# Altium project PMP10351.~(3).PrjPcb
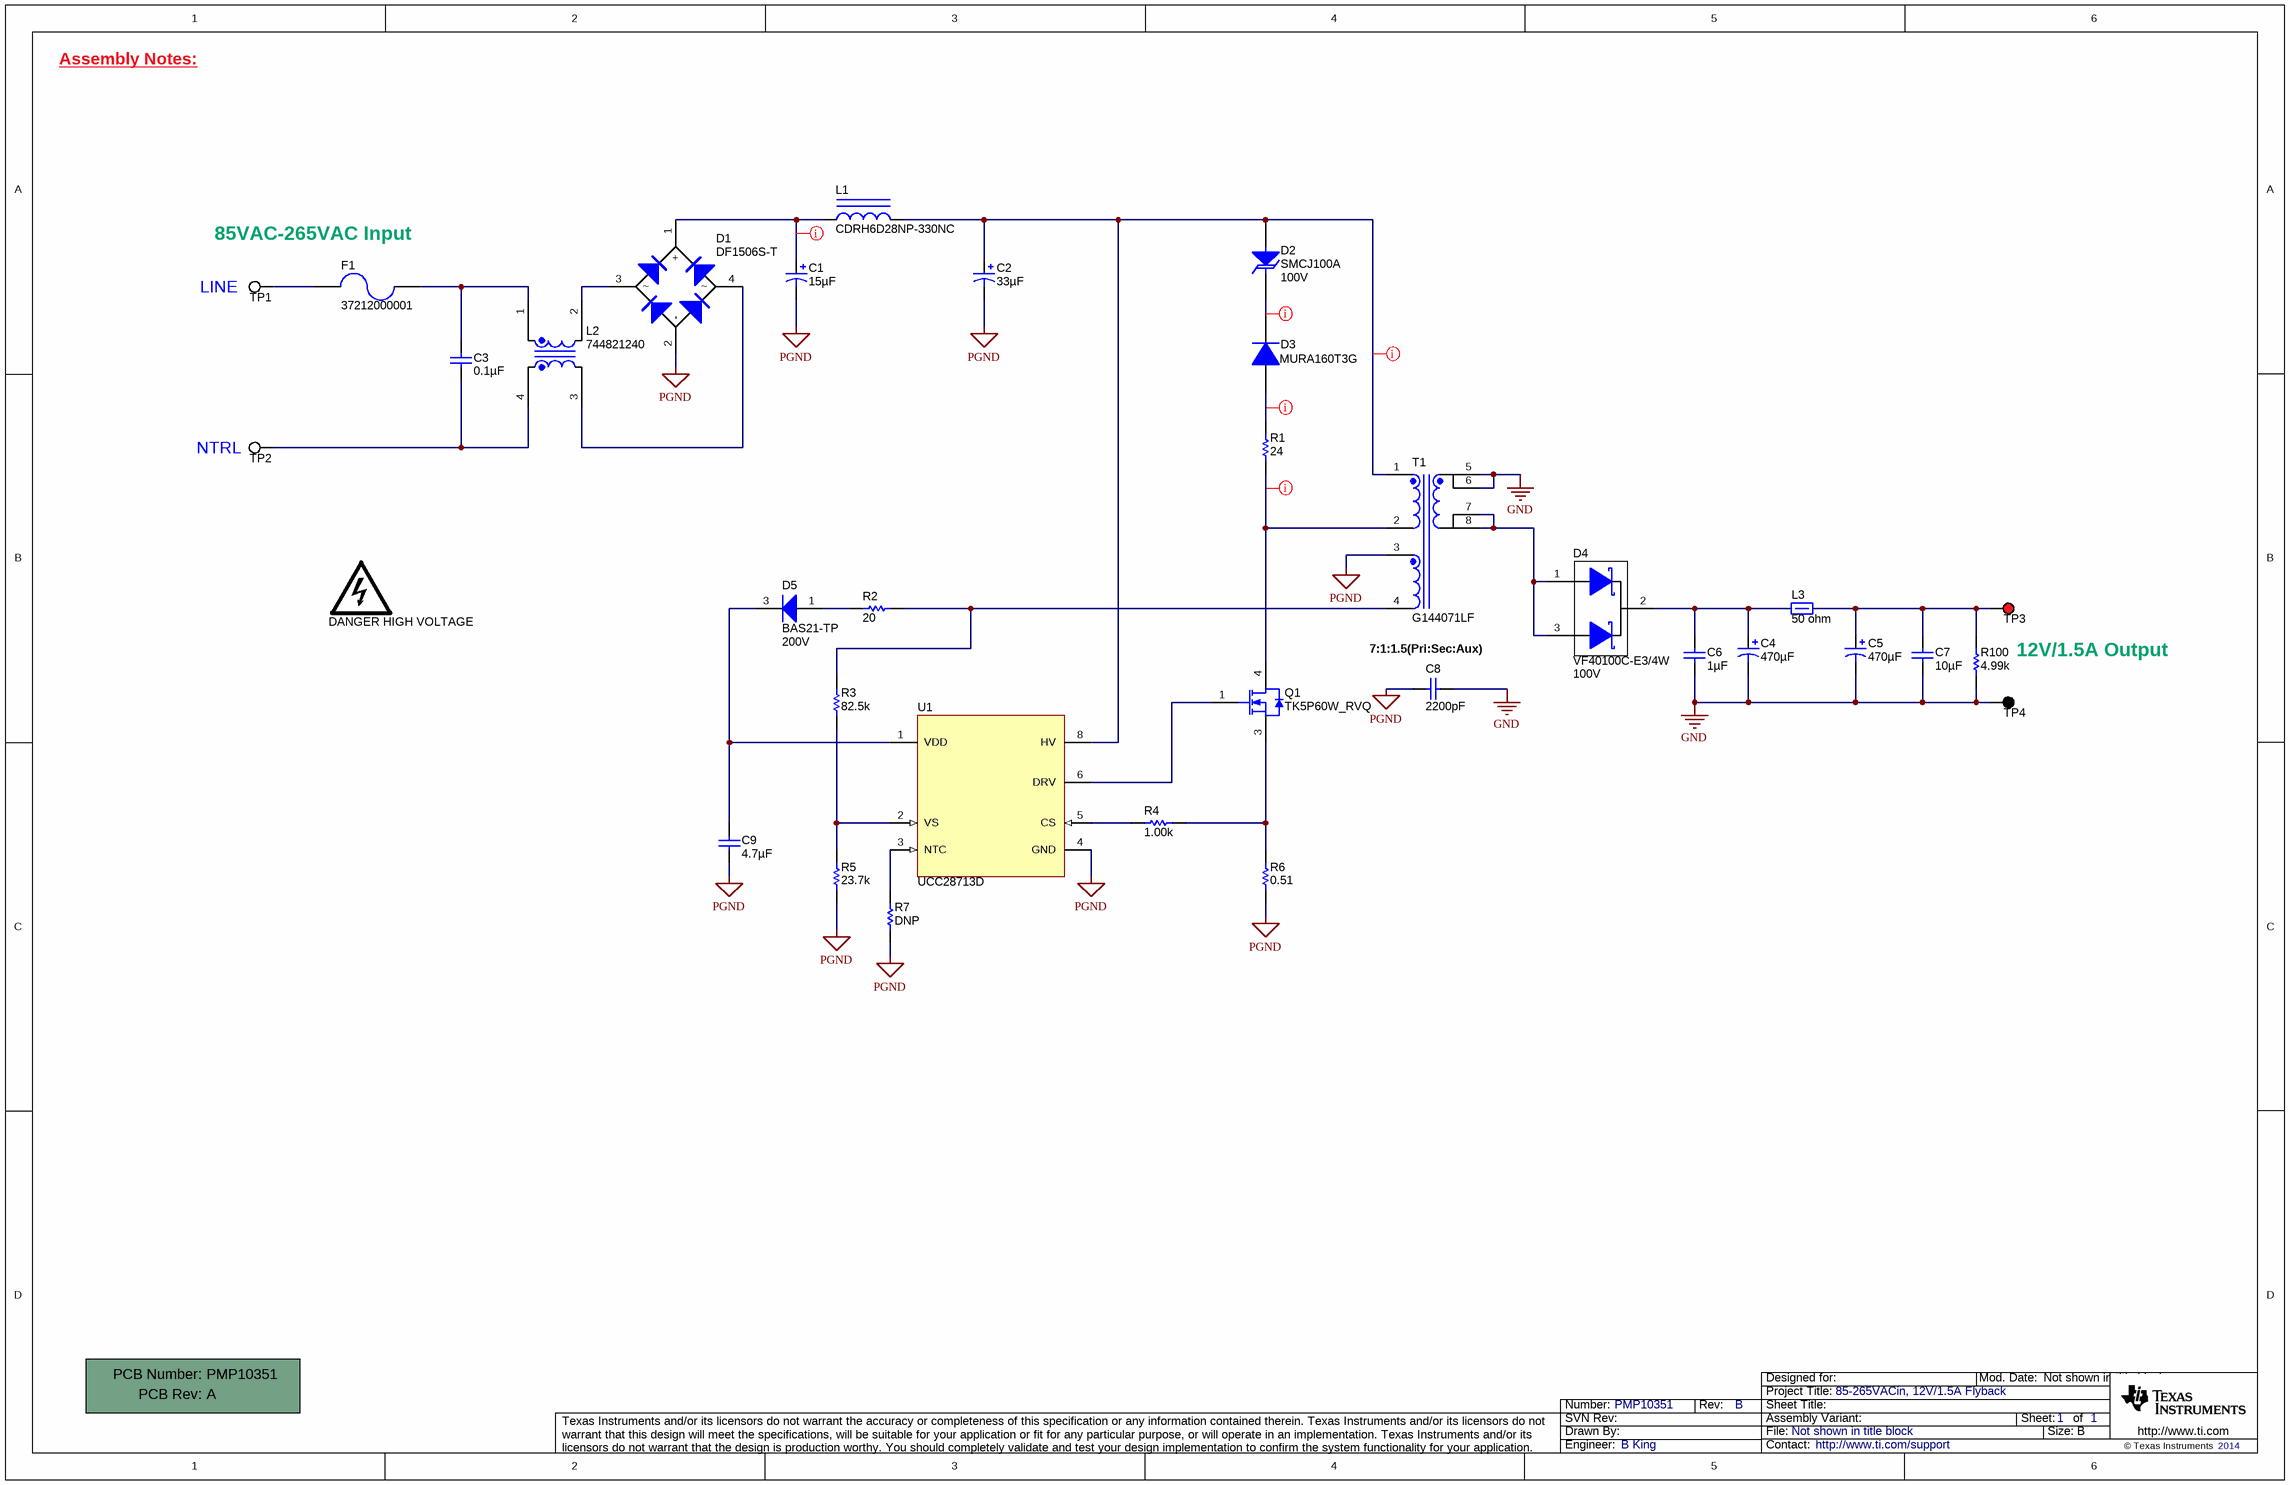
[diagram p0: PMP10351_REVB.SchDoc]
TechSupport: http://www.ti.com/support; SCH_Rev: B; PRJ_Title: 85-265VACin, 12V/1.5A Flyback; PRJ_Number: PMP10351; PRJ_Engineer: B King; PCB_Rev: A; PCB_Layout: B King; CopyrightYear: 2014
1 sheet, 35 parts. Net scope: global (net labels, ports and power ports of the same name join across sheets).
Board file: PMP10351_REVA.PcbDoc

## Sheet PMP10351_REVB.SchDoc
size 431 x 279 mm; Date: Not shown in title block; ApprovedBy: Not shown in title block; CheckedBy: Not shown in title block; Author: Not shown in title block; CompanyName: Not shown in title block; Engineer: Not shown in title block; Organization: Not shown in title block; Address1: Not shown in title block; Address2: Not shown in title block; Address3: Not shown in title block; Address4: Not shown in title block; DocumentNumber: 1; Revision: Use project parameter SCH_Rev; SheetNumber: 1; SheetTotal: 1; PageSetup: Record=PageOptions¦CenterHorizontal=True¦CenterVertical=True¦PrintScale=1.00¦XCorrection=1.00¦YCorrection=1.00¦PrintKind=0¦BorderSize=5000000¦LeftOffset=0¦BottomOffset=0¦Orientation=2¦PaperLength=1000¦PaperWidth=1000¦Scale=100¦PaperSource=15¦PrintQuality=600¦MediaType=1¦DitherType=10¦PaperKind=Letter¦PrintScaleMode=1

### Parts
!PCB1  Printed Circuit Board  (value not drawn)  (mechanical)
C1  ValueDisplayed: 15µF  [CAPPR5-12.5X20]  (hidden comment: EEUED2G150)
C2  ValueDisplayed: 33µF  [CAPPR7.5-16X20]  (hidden comment: EEUED2G330S)
C3  ValueDisplayed: 0.1µF  [B32922_10.5mm]  (hidden comment: B32922C3104M)
C4  ValueDisplayed: 470µF  [ZLG_800x1600]  (hidden comment: 16ZLG470MEFC8X16)
C5  ValueDisplayed: 470µF  [ZLG_800x1600]  (hidden comment: 16ZLG470MEFC8X16)
C6  ValueDisplayed: 1µF  [0603L]  (hidden comment: GRM188R61E105KA12D)
C7  ValueDisplayed: 10µF  [0805L]  (hidden comment: GRM21BR61E106MA73)
C8  ValueDisplayed: 2200pF  [CAPRD500W60D800H850]  (hidden comment: DE2E3KY222MA2BM01)
C9  ValueDisplayed: 4.7µF  [1206L]  (hidden comment: GRM319R61H475KA12)
D1  DF1506S-T  [DF-S]
D2  SMCJ100A  value 100V  [SMC]
D3  MURA160T3G  [SMA]
D4  VF40100C-E3/4W  value 100V  [TO-220AB]
D5  BAS21-TP  value 200V  [SOT-23L]
F1  37212000001  [FUSE_372]
L1  CDRH6D28NP-330NC  [CDRH6D28]
L2  744821240  [WE-CMB_XS]
L3  value 50 ohm  [1206L]  (hidden comment: HI1206T500R-10)
LOGO1  DANGER HIGH VOLTAGE  [IEC_HighVoltage_Small]  (no BOM)
Q1  TK5P60W_RVQ  [DPAK]
R1  value 24  [2010L]  (hidden comment: CRCW201024R0JNEF)
R2  ValueDisplayed: 20  [0603L]  (hidden comment: CRCW060320R0JNEA)
R3  ValueDisplayed: 82.5k  [0402L]  (hidden comment: CRCW040282K5FKED)
R4  ValueDisplayed: 1.00k  [0402L]  (hidden comment: CRCW04021K00FKED)
R5  ValueDisplayed: 23.7k  [0402L]  (hidden comment: CRCW040223K7FKED)
R6  value 0.51  [0805L]  (hidden comment: CRM0805-FX-R510ELF)
R7  value DNP  [0603L]  (hidden comment: N/A)
R100  ValueDisplayed: 4.99k  [0402L]  (hidden comment: CRCW04024K99FKED)
T1  G144071LF  [GCI_G144071LF]
TP1  5012  [Keystone5012]  (value not drawn)
TP2  5012  [Keystone5012]  (value not drawn)
TP3  5010  [Keystone5010]  (value not drawn)
TP4  5011  [Keystone5011]  (value not drawn)
U1  UCC28713D  [D0007A_L]

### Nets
GND: C4.2(-) C5.2(-) C6.2 C7.2 C8.1 R100.2 T1.5 T1.6 TP4.1
PGND: C1.2(-) C2.2(-) C8.2 C9.2 D1.2(-) R5.1 R6.1 R7.1 T1.3 U1.4(GND)
NetC1_1: C1.1(+) D1.1(+) L1.1
NetC2_1: C2.1(+) D2.2(A) L1.2 T1.1 U1.8(HV)
NetC3_1: C3.1 F1.1 L2.1
NetC3_2: C3.2 L2.4 TP2.1
NetC4_1: C4.1(+) C6.1 D4.2(K) L3.1
NetC5_1: C5.1(+) C7.1 L3.2 R100.1 TP3.1
NetC9_1: C9.1 D5.3(K) U1.1(VDD)
NetD1_3: D1.3 L2.2
NetD1_4: D1.4 L2.3
NetD2_1: D2.1(K) D3.1(K)
NetD3_2: D3.2(A) R1.2
NetD4_1: D4.1(A) D4.3(A) T1.7 T1.8
NetD5_1: D5.1(A) R2.2
NetF1_2: F1.2 TP1.1
NetQ1_1: Q1.1(G) U1.6(DRV)
NetQ1_3: Q1.3(S) R4.1 R6.2
NetQ1_4: Q1.4(D) R1.1 T1.2
NetR2_1: R2.1 R3.2 T1.4
NetR3_1: R3.1 R5.2 U1.2(VS)
NetR4_2: R4.2 U1.5(CS)
NetR7_2: R7.2 U1.3(NTC)

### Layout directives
rule Clearance Constraint [Clearance = 24mil]: NetQ1_4
rule Clearance Constraint [Clearance = 25mil]: NetC1_1, NetC2_1, NetD2_1, NetD3_2

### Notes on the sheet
- Assembly Notes:
- 85VAC-265VAC Input
- (near TP1) LINE
- (near TP2) NTRL
- 7:1:1.5(Pri:Sec:Aux)
- 12V/1.5A Output

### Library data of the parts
!PCB1 = PCB: Manufacturer: Any; PartNumber: PMP10351; SymbolCreator: a0412235
C1 = EEUED2G150: CAP, AL, 15uF, 400V, +/-20%, 1.909859 ohm, TH; Manufacturer: Panasonic; Polarized: Y; CompType: Capacitor; U/M: EA; Cap_F: 0.000015; Tolerance_%: 20; VDC_V: 400; IRMS_A: 0.41; TaMin_C: -25; TaMax_C: 105; AC_Derating: 0.3
C2 = EEUED2G330S: CAP, AL, 33 µF, 400 V, +/- 20%, 0.868117 ohm, TH; Manufacturer: Panasonic; Polarized: Y; CompType: Capacitor; Value: 33uF; U/M: EA; Cap_F: 0.000033; Tolerance_%: 20; VDC_V: 400; Value2: 400V; IRMS_A: 0.73; TaMin_C: -25; TaMax_C: 105; AC_Derating: 0.3
C3 = B32922C3104M: CAP, Film, 0.1 µF, 630 V, +/- 20%, TH; Manufacturer: EPCOS Inc; Polarized: N; CompType: Capacitor; Value: 0.1uF; U/M: EA; Cap_F: 0.0000001; Tolerance_%: 20; Value1: Unknown; VDC_V: 630; Value2: 630V; TaMax_C: 110
C4 C5 = 16ZLG470MEFC8X16: CAP, AL, 470 µF, 16 V, +/- 20%, 0.028 ohm, TH; Manufacturer: Rubycon; Polarized: Y; CompType: Capacitor; Value: 470uF; U/M: EA; Cap_F: 0.00047; Tolerance_%: 20; VDC_V: 16; Value2: 16V; ESR_ohm: 0.028; IRMS_A: 1.25; TaMin_C: -40; TaMax_C: 105; Cap_Case: 8x16mm
C6 = GRM188R61E105KA12D: CAP, CERM, 1 µF, 25 V, +/- 10%, X5R, 0603; Manufacturer: MuRata; Polarized: N; CompType: Capacitor; Value: 1uF; U/M: EA; Cap_F: 0.000001; Tolerance_%: 10; Value1: Unknown; VDC_V: 25; Value2: 25V; TaMin_C: -55; TaMax_C: 85; Cap_Case: 0603
C7 = GRM21BR61E106MA73: CAP, CERM, 10 µF, 25 V, +/- 20%, X5R, 0805; Manufacturer: MuRata; Polarized: N; CompType: Capacitor; Value: 10uF; U/M: EA; Cap_F: 0.00001; Tolerance_%: 20; Value1: Unknown; VDC_V: 25; Value2: 25V; TaMin_C: -55; TaMax_C: 85; Cap_Case: 0805
C8 = DE2E3KY222MA2BM01: CAP, CERM, 2200pF, 250V, +/-20%, KY, Radial D8x5mm; Manufacturer: MuRata; Polarized: N; CompType: Capacitor; U/M: EA; Cap_F: 0.0000000022; Tolerance_%: 20; Value1: Unknown; VDC_V: 250; TaMin_C: -25; TaMax_C: 85
C9 = GRM319R61H475KA12: CAP, CERM, 4.7 µF, 50 V, +/- 10%, X5R, 1206; Manufacturer: MuRata; Polarized: N; CompType: Capacitor; Value: 4.7uF; U/M: EA; Cap_F: 0.0000047; Tolerance_%: 10; Value1: Unknown; VDC_V: 50; Value2: 50V; TaMin_C: -55; TaMax_C: 85; Cap_Case: 1206
D1 = DF1506S-T: Diode, Switching-Bridge, 600V, 1.5A, DF-S; Manufacturer: Diodes Inc.; Value: 1.1V; U/M: EA; Vf_V: 1.1; Io_A: 1.5; Vr_V: 600; TJmax_C: 150
D2 = SMCJ100A: Diode, TVS, Uni, 100V, 1500W, SMC; Manufacturer: Littelfuse; U/M: EA; Power_W: 1500; Vr_V: 100; RJA_CperW: 75
D3 = MURA160T3G: Diode, Ultrafast, 600V, 1A, SMA; Manufacturer: ON Semiconductor; Value: 1.05V; U/M: EA; Vf_V: 1.05; Io_A: 1; Vr_V: 600; TJmax_C: 175
D4 = VF40100C-E3/4W: Diode, Schottky, 100V, 20A, TH; Manufacturer: Vishay-Semiconductor; SymbolCreator: a0411947; U/M: EA; Vf_V: 0.73; Value2: 0.73V; Io_A: 20; Vr_V: 100; TJmax_C: 150; RJC_CperW: 2
D5 = BAS21-TP: Diode, P-N, 200V, 200A, SOT-23; Manufacturer: Micro Commercial Components; U/M: EA; Vf_V: 1.25; Io_A: 200; Value2: 1.25V; TJmax_C: 150; RJC_CperW: 430
F1 = 37215000001: Fuse, 2A, 250V, TH; Manufacturer: Littelfuse; U/M: EA; OpeningTime_100%_min: 4; OpeningTime_200%_max: 2; VDC_V: 250; Irating_A: 5; MeltingTyp: 94; Vdrop: 0.08; Soldering_Wave_MaxTemp_C: 260
L1 = CDRH6D28NP-330NC: Inductor, Shielded Drum Core, Ferrite, 33uH, 0.97A, 0.165 ohm, SMD; Manufacturer: Sumida; Ind_H: 33.0E-6; ValueDisplayed: 33µH; Imax_A: 0.97; Irms: 0.97A @ 30C rise; Isat: 0.97A @ 35% inductance drop; DCR_ohm: 0.165; U/M: EA
L2 = 744821240: Coupled inductor, 4000uH, 1.5A, 0.14 ohm, +/-30%, TH; Manufacturer: Wurth Elektronik eiSos; SymbolCreator: a0412235; Ind_H: 0.004; DCR_Ohm: 0.14; Isat: 1.5; Tolerance_%: 30; U/M: EA
L3 = HI1206T500R-10: Ferrite Bead, 50 ohm @ 100MHz, 6A, 1206; Manufacturer: Laird-Signal Integrity Products; Imax_A: 6; DCR_ohm: 0.01; Value1: 0.01 ohm; ZTyp@100MHz_Ohm: 50; Ztyp@1GHz_Ohm: 70
LOGO1 = IEC_HighVoltage: IEC 61010-1 High Voltage Warning; SymbolCreator: a0412235
Q1 = TK5P60W_RVQ: MOSFET, N-CH, 600V, 5.4A, DPAK; Manufacturer: Toshiba; Alternate Manufacturer: None; U/M: EA; ChType: N; VdsMax_V: 600; Value1: ? ohm; Value2: 10.5 nC; QgTyp_nC: 10.5; Vgs_V: 30; IdsMax_A: 5.4
R1 = CRCW201024R0JNEF: RES, 24 ohm, 5%, 0.75W, 2010; Manufacturer: Vishay-Dale; CompType: Resistor; Value_Code: 24R0; Tolerance_%: 5; Power_W: 0.75; VDC_V: 400; TempCo: 200 ppm/C; EIA_Code: E24; U/M: EA
R2 = CRCW060320R0JNEA: RES, 20, 5%, 0.1 W, 0603; Manufacturer: Vishay-Dale; CompType: Resistor; Value: 20; Value_Code: 20R0; Tolerance_%: 5; Power_W: 0.1; Value2: 0.1W; VDC_V: 75; TempCo: 200 ppm/C; EIA_Code: E24; U/M: EA
R3 = CRCW040282K5FKED: RES, 82.5 k, 1%, 0.063 W, 0402; Manufacturer: Vishay-Dale; CompType: Resistor; Value: 82.5k; Res_ohm: 82500; Value_Code: 82k5; Tolerance_%: 1; Power_W: 0.063; Value2: 0.063W; VDC_V: 50; TempCo: 100 ppm/C; EIA_Code: E96; U/M: EA
R4 = CRCW04021K00FKED: RES, 1.00 k, 1%, 0.063 W, 0402; Manufacturer: Vishay-Dale; CompType: Resistor; Value: 1.00k; Res_ohm: 1000; Value_Code: 1k00; Tolerance_%: 1; Power_W: 0.063; Value2: 0.063W; VDC_V: 50; TempCo: 100 ppm/C; EIA_Code: E96; U/M: EA
R5 = CRCW040223K7FKED: RES, 23.7 k, 1%, 0.063 W, 0402; Manufacturer: Vishay-Dale; CompType: Resistor; Value: 23.7k; Res_ohm: 23700; Value_Code: 23k7; Tolerance_%: 1; Power_W: 0.063; Value2: 0.063W; VDC_V: 50; TempCo: 100 ppm/C; EIA_Code: E96; U/M: EA
R6 = CRM0805-FX-R510ELF: RES, 0.51 ohm, 1%, 0.25W, 0805; Manufacturer: Bourns; CompType: Resistor; Value_Code: R510; Tolerance_%: 1; Power_W: 0.25; VDC_V: 0; TempCo: 100 ppm/C; EIA_Code: E96; U/M: EA
R7 = CRCW06030000Z0EA: Do Not Populate; CompType: Resistor; Res_ohm: 0; Value_Code: 0000; Tolerance_%: 5; Value1: 5%; Power_W: 0.1; Value2: 0.1W; VDC_V: 75; TempCo: 200 ppm/C; EIA_Code: E24; U/M: EA
R100 = CRCW04024K99FKED: RES, 4.99 k, 1%, 0.063 W, 0402; Manufacturer: Vishay-Dale; CompType: Resistor; Value: 4.99k; Res_ohm: 4990; Value_Code: 4k99; Tolerance_%: 1; Power_W: 0.063; Value2: 0.063W; VDC_V: 50; TempCo: 100 ppm/C; EIA_Code: E96; U/M: EA
T1 = G144071LF: Transformer, 400 uH, TH; Manufacturer: GCI Technologies; SymbolCreator: Altium; DCR_Ohm: 1; Value: 400 uH; LeakageL: 6 uH; U/M: EA
TP1 TP2 = 5012: Test Point, Multipurpose, White, TH; Manufacturer: Keystone; CompType: Test Point Loop; U/M: EA
TP3 = 5010: Test Point, Multipurpose, Red, TH; Manufacturer: Keystone; CompType: Test Point Loop; U/M: EA
TP4 = 5011: Test Point, Multipurpose, Black, TH; Manufacturer: Keystone; CompType: Test Point Loop; U/M: EA
U1 = UCC28713D: Constant-Voltage, Constant-Current Controller With Primary-Side Regulation, D0007A; Alternate Manufacturer: None; Manufacturer: Texas Instruments; SymbolCreator: Altium; CompType: IC; U/M: EA

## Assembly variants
001: not fitted FID1 FID2 FID3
